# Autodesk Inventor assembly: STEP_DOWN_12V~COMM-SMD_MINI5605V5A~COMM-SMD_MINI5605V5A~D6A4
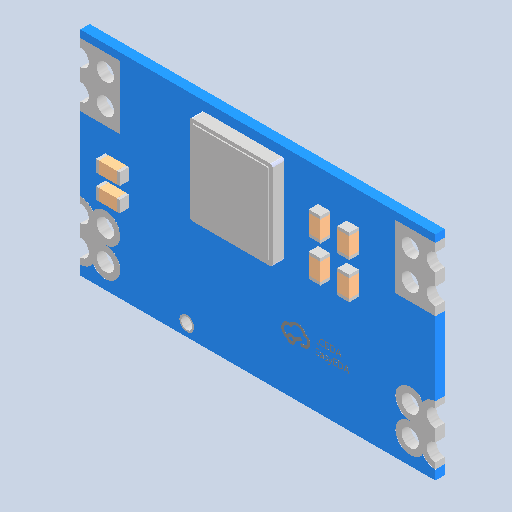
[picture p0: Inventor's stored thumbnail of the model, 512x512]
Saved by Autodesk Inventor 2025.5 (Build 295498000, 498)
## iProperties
Created: 2026-10
Part Number: STEP_DOWN_12V~COMM-SMD_MINI5605V5A~COMM-SMD_MINI5605V5A~D6A4
Document SubType Name: Assembly
Designer: Luis M
Author: Luis M
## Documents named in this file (2)
- C:\Users\Luis M\Downloads\3D_PCB1_2026-10-28\STEP_DOWN_12V~COMM-SMD_MINI5605V5A~COMM-SMD_MINI5605V5A~D6A4.iam
- C:\Users\Luis M\Downloads\3D_PCB1_2026-10-28\COMM-SMD_MINI5605V5A~COMM-SMD_MINI5605V5A~t0xY.ipt
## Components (1 placed, 1 different names)
1. STEP_DOWN_12V->0
